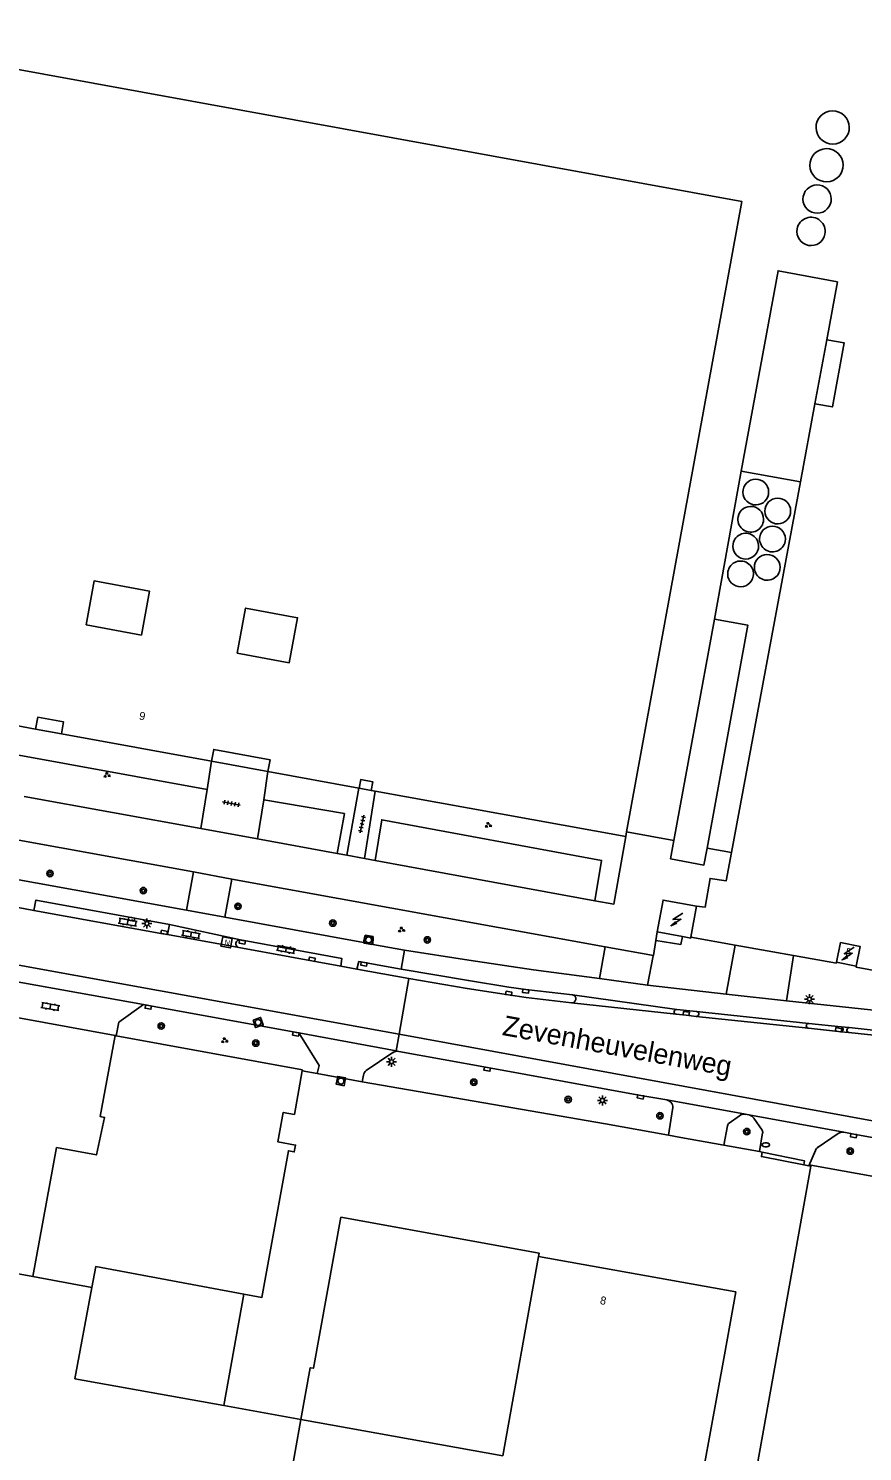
# Model space of a CAD drawing. Extents: x 130998 to 133001, y 398999 to 403002.
# Drawn here: x 132503.7 to 132608, y 399481.4 to 399659.2 of the extents above; entities that cross this region are included whole.
import ezdxf

# ---------------------------------------------------------------- set-up
doc = ezdxf.new("R2010")
doc.units = 0
for name, color, linetype in [('gg-afsc-erfafscheiding', 7, 'Continuous'), ('gg-afsc-hekwerk', 7, 'Continuous'), ('gg-anno-huisnummerreeks BGT', 7, 'Continuous'), ('gg-anno-openbare ruimte label', 7, 'Continuous'), ('gg-bbg-bijgebouw', 7, 'Continuous'), ('gg-bbg-gedigitaliseerde bebouwing', 7, 'Continuous'), ('gg-bbg-hoofdgebouw', 7, 'Continuous'), ('gg-bbg-luifel en loopbrug', 7, 'Continuous'), ('gg-bbg-opslagtank', 7, 'Continuous'), ('gg-bbg-tussenscheiding', 7, 'Continuous'), ('gg-knt-verharding', 7, 'Continuous'), ('gg-knt-verharding nz', 7, 'Continuous'), ('gt-grn-groengrens', 7, 'Continuous'), ('gt-grn-weggrens', 7, 'Continuous'), ('gt-symb-boom', 7, 'Continuous'), ('gt-symb-brandkraan', 7, 'Continuous'), ('gt-symb-groenvak', 7, 'Continuous'), ('gt-symb-klinker verharding', 7, 'Continuous'), ('gt-symb-kolk', 7, 'Continuous'), ('gt-symb-lichtmast', 7, 'Continuous'), ('gt-symb-nortonput', 7, 'Continuous'), ('gt-symb-rioolschacht', 7, 'Continuous'), ('gt-symb-tegel verharding', 7, 'Continuous'), ('gt-symb-trafo symbool', 7, 'Continuous')]:
    doc.layers.add(name, color=color, linetype=linetype)

# ---------------------------------------------------------------- blocks, each defined once
blk = doc.blocks.new('gt0-GRVAK')
at = {"layer": 'gt-symb-groenvak'}
for p, q in [((-0.11, 0.19), (-0.23, 0.24)), ((-0.18, 0.15), (0.09, 0.15)), ((-0.09, 0.21), (-0.16, 0.32)), ((-0.05, 0.21), (-0.05, 0.39)), ((0, 0.21), (0.06, 0.32)), ((0.01, 0.19), (0.13, 0.24)), ((0.26, -0.05), (0.2, 0.06)), ((0.3, -0.05), (0.3, 0.13)), ((0.35, -0.05), (0.41, 0.06)), ((-0.24, -0.23), (-0.36, -0.18)), ((-0.32, -0.26), (-0.05, -0.26)), ((-0.23, -0.21), (-0.29, -0.09)), ((-0.18, -0.2), (-0.18, -0.02)), ((-0.14, -0.21), (-0.07, -0.09)), ((-0.12, -0.23), (0, -0.18)), ((0.24, -0.07), (0.12, -0.02)), ((0.17, -0.11), (0.44, -0.11)), ((0.37, -0.07), (0.49, -0.02))]:
    blk.add_line(p, q, dxfattribs=at)
blk = doc.blocks.new('gt0-TEG1')
at = {"layer": 'gt-symb-tegel verharding'}
for p, q in [((-1.12, 0), (1.12, 0)), ((-0.9, -0.25), (-0.9, 0.25)), ((-0.45, -0.25), (-0.45, 0.25)), ((0, -0.25), (0, 0.25)), ((0.45, -0.25), (0.45, 0.25)), ((0.9, -0.25), (0.9, 0.25))]:
    blk.add_line(p, q, dxfattribs=at)
blk = doc.blocks.new('gt0-BOOM')
at = {"layer": 'gt-symb-boom'}
for radius in [0.4, 0.2]:
    blk.add_circle((0, 0), radius, dxfattribs=at)
blk = doc.blocks.new('gt0-RS')
at = {"layer": 'gt-symb-rioolschacht'}
blk.add_lwpolyline([(-0.5, -0.5), (0.5, -0.5), (0.5, 0.5), (-0.5, 0.5)], close=True, dxfattribs=at)
blk.add_circle((0, 0), 0.375, dxfattribs=at)
blk = doc.blocks.new('gt0-KL1')
at = {"layer": 'gt-symb-klinker verharding'}
for p, q in [((-1.15, 0.3), (1.15, 0.3)), ((-1, -0.3), (-1, 0.3)), ((-0.5, 0.3), (-0.5, 0.45)), ((0, -0.3), (0, 0.3)), ((0.5, 0.3), (0.5, 0.45)), ((1, -0.3), (1, 0.3)), ((-1.15, -0.3), (1.15, -0.3)), ((-0.5, -0.45), (-0.5, -0.3)), ((0.5, -0.45), (0.5, -0.3))]:
    blk.add_line(p, q, dxfattribs=at)
blk = doc.blocks.new('gt0-NPUT')
at = {"layer": 'gt-symb-nortonput'}
blk.add_lwpolyline([(-0.57, -0.61), (-0.57, 0.59), (0.63, 0.59), (0.63, -0.61)], close=True, dxfattribs=at)
blk.add_text('N', height=0.7, dxfattribs=at).set_placement((-0.22, -0.38))
blk = doc.blocks.new('gt0-KOLK')
at = {"layer": 'gt-symb-kolk'}
blk.add_lwpolyline([(0, 0), (0.37, 0), (0.37, 0.4), (-0.38, 0.4), (-0.38, 0), (0, 0)], dxfattribs=at)
blk = doc.blocks.new('gt0-LMAST')
at = {"layer": 'gt-symb-lichtmast'}
for p, q in [((-0.18, 0.17), (-0.45, 0.44)), ((-0.01, 0.25), (-0.01, 0.62)), ((0.17, 0.17), (0.44, 0.44)), ((-0.26, 0), (-0.63, 0)), ((-0.18, -0.18), (-0.45, -0.45)), ((-0.01, -0.25), (-0.01, -0.63)), ((0.44, -0.45), (0.17, -0.18)), ((0.24, 0), (0.62, 0))]:
    blk.add_line(p, q, dxfattribs=at)
blk.add_circle((-0.01, 0), 0.25, dxfattribs=at)
blk = doc.blocks.new('gt0-HSP')
at = {"layer": 'gt-symb-trafo symbool'}
for points in [[(0.77, 0.75), (-0.53, 0), (0.47, 0), (-0.83, -0.75)], [(-0.22, -0.24), (-0.83, -0.75), (-0.08, -0.48)]]:
    blk.add_lwpolyline(points, dxfattribs=at)
blk = doc.blocks.new('gt0-BR')
at = {"layer": 'gt-symb-brandkraan'}
for centre, radius, start, end in [((-0.24, 0), 0.206, 107.5669, 252.4331), ((0.6, -2.66), 3, 106.892, 107.5669), ((0, -0.69), 0.938, 73.108, 106.892), ((-0.6, -2.66), 3, 72.4331, 73.108), ((0.24, 0), 0.206, 287.567, 72.4331), ((0.6, 2.66), 3, 252.4331, 253.108), ((0, 0.69), 0.938, 253.108, 286.8921), ((-0.6, 2.66), 3, 286.8921, 287.567)]:
    blk.add_arc(centre, radius, start, end, dxfattribs=at)

msp = doc.modelspace()

# ---------------------------------------------------------------- linework, layer by layer
at = {"layer": 'gg-afsc-erfafscheiding'}
msp.add_line((132497.49, 399536.49), (132514.58, 399533.36), dxfattribs=at)
at = {"layer": 'gg-afsc-hekwerk'}
for p, q in [((132578.49, 399558.81), (132584.42, 399557.73)), ((132591.62, 399556.25), (132588.56, 399556.8)), ((132586.54, 399545.66), (132592.08, 399544.67)), ((132592.08, 399544.67), (132599.35, 399543.38)), ((132539.84, 399528.64), (132537.96, 399528.96)), ((132545.43, 399527.59), (132539.84, 399528.64)), ((132583.74, 399520.91), (132585.27, 399520.63)), ((132590.66, 399519.66), (132585.27, 399520.63)), ((132595.1, 399518.86), (132590.66, 399519.66)), ((132595.46, 399518.8), (132595.1, 399518.86)), ((132601.27, 399517.07), (132600.66, 399517.19))]:
    msp.add_line(p, q, dxfattribs=at)
for points in [[(132599.35, 399543.38), (132604.74, 399542.42), (132604.76, 399542.54)], [(132624.88, 399538.68), (132607.19, 399541.92), (132607.21, 399542.04)], [(132545.43, 399527.59), (132575.85, 399522.32), (132583.74, 399520.91)], [(132600.66, 399517.19), (132595.36, 399518.24), (132595.46, 399518.8)]]:
    msp.add_lwpolyline(points, dxfattribs=at)
at = {"layer": 'gg-bbg-bijgebouw'}
for p, q in [((132603.52, 399620.32), (132604.85, 399627.58)), ((132602.05, 399612.33), (132603.52, 399620.32)), ((132600.26, 399602.55), (132602.05, 399612.33)), ((132592.83, 399603.91), (132600.26, 399602.55)), ((132589.47, 399585.42), (132584.42, 399557.73)), ((132586.54, 399545.66), (132587.24, 399549.54)), ((132582.33, 399546.31), (132585.48, 399545.74)), ((132514.68, 399533.34), (132514.58, 399533.36)), ((132537.98, 399529.08), (132514.68, 399533.34)), ((132537.98, 399529.08), (132537.96, 399528.96)), ((132530.66, 399501.05), (132528.15, 399487.13)), ((132528.15, 399487.13), (132537.79, 399485.39))]:
    msp.add_line(p, q, dxfattribs=at)
for points in [[(132604.85, 399627.58), (132597.43, 399628.94), (132592.83, 399603.91)], [(132588.56, 399556.8), (132593.64, 399584.66), (132589.47, 399585.42)], [(132584.42, 399557.73), (132584, 399555.43), (132588.17, 399554.67), (132588.56, 399556.8)], [(132587.24, 399549.54), (132583.07, 399550.3), (132582.33, 399546.31)], [(132585.48, 399545.74), (132586.52, 399545.55), (132586.54, 399545.66)], [(132504.29, 399503.24), (132507.25, 399519.36), (132512.22, 399518.44), (132513.24, 399523.13), (132512.7, 399523.23), (132514.58, 399533.36)], [(132537.96, 399528.96), (132536.97, 399523.5), (132535.58, 399523.75), (132534.92, 399520.08), (132537.12, 399519.68), (132536.96, 399518.82), (132536.22, 399518.96), (132532.92, 399500.64), (132530.66, 399501.05)], [(132613.38, 399468.91), (132593.54, 399472.44), (132601.52, 399517.03)], [(132601.52, 399517.03), (132601.55, 399517.17), (132621.47, 399513.6)], [(132537.79, 399485.39), (132538.95, 399491.85), (132539.36, 399491.78), (132542.76, 399510.66)], [(132567.51, 399505.77), (132567.58, 399506.15), (132542.76, 399510.66)], [(132479.5, 399469.15), (132486.41, 399506.55), (132504.29, 399503.24)]]:
    msp.add_lwpolyline(points, dxfattribs=at)
at = {"layer": 'gg-bbg-gedigitaliseerde bebouwing'}
for points in [[(132510.93, 399584.68), (132517.85, 399583.41), (132518.86, 399588.92), (132511.94, 399590.19), (132510.93, 399584.68)], [(132529.84, 399581.15), (132536.34, 399579.96), (132537.37, 399585.59), (132530.87, 399586.78), (132529.84, 399581.15)]]:
    msp.add_lwpolyline(points, dxfattribs=at)
at = {"layer": 'gg-bbg-hoofdgebouw'}
for p, q in [((132459.74, 399579.83), (132504.62, 399571.67)), ((132507.85, 399571.08), (132526.63, 399567.64)), ((132533.66, 399566.36), (132545.04, 399564.29)), ((132545.04, 399564.29), (132545.08, 399564.28)), ((132546.57, 399564.01), (132547.06, 399563.92)), ((132547.06, 399563.92), (132578.39, 399558.23)), ((132578.39, 399558.23), (132578.49, 399558.81)), ((132604.76, 399542.54), (132607.21, 399542.04)), ((132592.17, 399501.33), (132567.51, 399505.77))]:
    msp.add_line(p, q, dxfattribs=at)
for points in [[(132578.49, 399558.81), (132592.89, 399637.61), (132474.31, 399659.23)], [(132504.62, 399571.67), (132504.89, 399573.15), (132508.12, 399572.57), (132507.85, 399571.08)], [(132526.63, 399567.64), (132526.9, 399569.12), (132533.93, 399567.84), (132533.66, 399566.36)], [(132545.08, 399564.28), (132545.28, 399565.35), (132546.76, 399565.08), (132546.57, 399564.01)], [(132607.21, 399542.04), (132607.71, 399544.49), (132605.26, 399544.99), (132604.76, 399542.54)], [(132592.17, 399501.33), (132590.74, 399493.44), (132586.45, 399469.96)]]:
    msp.add_lwpolyline(points, dxfattribs=at)
at = {"layer": 'gg-bbg-luifel en loopbrug'}
msp.add_lwpolyline([(132603.52, 399620.32), (132605.7, 399619.92), (132604.24, 399611.93), (132602.05, 399612.33)], dxfattribs=at)
at = {"layer": 'gg-bbg-opslagtank'}
for centre, radius, start, end in [((132604.26, 399646.86), 2.08, 349.4438, 169.4218), ((132604.26, 399646.86), 2.08, 169.4489, 349.4167), ((132603.49, 399642.13), 2.08, 349.4489, 169.4167), ((132603.49, 399642.14), 2.08, 169.4438, 349.4218), ((132602.32, 399637.91), 1.77, 169.425, 349.425), ((132602.32, 399637.91), 1.77, 349.425, 169.425), ((132601.56, 399633.86), 1.77, 349.428, 169.4538), ((132601.56, 399633.86), 1.77, 169.4597, 349.422), ((132594.65, 399601.29), 1.61, 349.4295, 169.4295), ((132594.65, 399601.29), 1.61, 169.4295, 349.4295), ((132594.02, 399597.89), 1.61, 349.4852, 169.4852), ((132597.4, 399598.92), 1.61, 169.4295, 349.4295), ((132597.4, 399598.92), 1.61, 349.4295, 169.4295), ((132594.02, 399597.89), 1.61, 169.4852, 349.4852), ((132593.39, 399594.53), 1.61, 349.412, 169.4535), ((132596.74, 399595.42), 1.61, 169.4852, 349.4852), ((132596.74, 399595.42), 1.61, 349.4852, 169.4852), ((132593.39, 399594.53), 1.61, 169.4535, 349.412), ((132592.75, 399591.06), 1.61, 349.447, 169.4885), ((132596.08, 399591.88), 1.61, 169.4502, 349.4502), ((132596.08, 399591.88), 1.61, 349.4502, 169.4502), ((132592.75, 399591.06), 1.61, 169.482, 349.4535)]:
    msp.add_arc(centre, radius, start, end, dxfattribs=at)
at = {"layer": 'gg-bbg-tussenscheiding'}
for p, q in [((132567.51, 399505.77), (132563.02, 399480.85)), ((132504.29, 399503.24), (132511.66, 399501.88)), ((132537.79, 399485.39), (132533.05, 399459.11)), ((132537.79, 399485.39), (132563.02, 399480.85))]:
    msp.add_line(p, q, dxfattribs=at)
for points in [[(132511.66, 399501.88), (132512.14, 399504.48), (132530.66, 399501.05)], [(132528.15, 399487.13), (132509.55, 399490.48), (132511.66, 399501.88)]]:
    msp.add_lwpolyline(points, dxfattribs=at)
at = {"layer": 'gg-knt-verharding'}
for p, q in [((132589.47, 399585.42), (132592.83, 399603.91)), ((132600.26, 399602.55), (132591.62, 399556.25)), ((132461.47, 399575.83), (132526.06, 399564.12)), ((132526.06, 399564.12), (132526.63, 399567.64)), ((132457.72, 399565.92), (132524.37, 399553.82)), ((132533.66, 399566.36), (132533.16, 399562.82)), ((132523.48, 399549.02), (132441.68, 399563.91)), ((132525.26, 399559.23), (132526.06, 399564.12)), ((132543.55, 399555.89), (132545.04, 399564.29)), ((132547.06, 399563.92), (132545.75, 399555.48)), ((132503.18, 399563.26), (132525.26, 399559.23)), ((132532.38, 399557.93), (132533.16, 399562.82)), ((132525.26, 399559.23), (132532.38, 399557.93)), ((132542.32, 399556.11), (132543.55, 399555.89)), ((132543.55, 399555.89), (132545.75, 399555.48)), ((132545.75, 399555.48), (132547.09, 399555.24)), ((132523.48, 399549.02), (132524.37, 399553.82)), ((132529.16, 399552.93), (132528.28, 399548.16)), ((132575.84, 399544.44), (132529.16, 399552.93)), ((132502.45, 399549.36), (132504.42, 399549)), ((132504.42, 399549), (132520.53, 399546.08)), ((132523.48, 399549.02), (132528.28, 399548.16)), ((132528.28, 399548.16), (132545.61, 399544.98)), ((132521.11, 399545.98), (132520.53, 399546.08)), ((132521.35, 399547.26), (132521.11, 399545.98)), ((132521.11, 399545.98), (132530.04, 399544.36)), ((132521.35, 399547.26), (132530.22, 399545.32)), ((132582.16, 399545.25), (132582.33, 399546.31)), ((132530.04, 399544.36), (132542.78, 399542.03)), ((132546.79, 399544.75), (132550.74, 399544.03)), ((132550.74, 399544.03), (132550.32, 399541.67)), ((132575.84, 399544.44), (132575.13, 399540.5)), ((132581.85, 399543.38), (132582.16, 399545.25)), ((132592.08, 399544.67), (132590.94, 399538.52)), ((132542.78, 399542.03), (132544.8, 399541.66)), ((132544.8, 399541.66), (132545.02, 399542.62)), ((132545.02, 399542.62), (132550.32, 399541.67)), ((132581.84, 399543.32), (132581.13, 399539.67)), ((132581.84, 399543.32), (132581.85, 399543.38)), ((132599.35, 399543.38), (132598.5, 399537.7)), ((132496.36, 399541.17), (132518.1, 399537.23)), ((132544.8, 399541.66), (132551.26, 399540.51)), ((132550.06, 399533.52), (132551.26, 399540.51)), ((132575.13, 399540.5), (132581.13, 399539.67)), ((132571.75, 399538.44), (132584.78, 399536.64)), ((132581.13, 399539.67), (132590.94, 399538.52)), ((132590.94, 399538.52), (132598.5, 399537.7)), ((132518.1, 399537.23), (132520.32, 399536.82)), ((132520.32, 399536.82), (132537.55, 399533.69)), ((132571.62, 399537.44), (132584.69, 399536.03)), ((132584.78, 399536.64), (132587.26, 399536.37)), ((132587.2, 399535.76), (132601.23, 399534.27)), ((132587.26, 399536.37), (132601.28, 399534.88)), ((132601.28, 399534.88), (132605.31, 399534.45)), ((132549.68, 399531.47), (132537.55, 399533.69)), ((132549.68, 399531.47), (132550.06, 399533.52)), ((132605.24, 399533.84), (132606.3, 399533.73)), ((132605.31, 399534.45), (132606.34, 399534.35)), ((132606.34, 399534.35), (132625.75, 399532.24)), ((132550.03, 399531.39), (132549.68, 399531.47)), ((132549.29, 399531.23), (132545.96, 399528.99)), ((132545.61, 399528.42), (132545.43, 399527.59)), ((132593.35, 399523.52), (132583.52, 399525.32)), ((132583.74, 399520.91), (132584.26, 399524.13)), ((132592.6, 399523.35), (132591.31, 399522.43)), ((132593.8, 399523.44), (132593.35, 399523.52)), ((132605.67, 399521.29), (132593.8, 399523.44)), ((132595.44, 399521.55), (132594.4, 399523.03)), ((132591.11, 399522.09), (132590.66, 399519.66)), ((132595.1, 399518.86), (132595.51, 399521.19)), ((132604.95, 399521.12), (132602.46, 399519.43)), ((132602.11, 399519.01), (132601.27, 399517.07)), ((132601.27, 399517.07), (132601.52, 399517.03))]:
    msp.add_line(p, q, dxfattribs=at)
for points in [[(132542.32, 399556.11), (132543.23, 399561.11), (132533.16, 399562.82)], [(132547.09, 399555.24), (132547.89, 399560.33), (132575.38, 399555.25), (132574.55, 399550.22)], [(132574.55, 399550.22), (132576.91, 399549.79), (132578.39, 399558.23)], [(132591.62, 399556.25), (132590.96, 399552.71), (132588.94, 399553.01), (132588.33, 399549.42), (132587.24, 399549.54)], [(132521.35, 399547.26), (132504.67, 399550.3), (132504.42, 399549)], [(132545.61, 399544.98), (132545.77, 399545.77), (132546.84, 399545.57), (132546.79, 399544.75)], [(132585.48, 399545.74), (132585.28, 399544.74), (132582.16, 399545.25)], [(132530.22, 399545.32), (132542.92, 399542.99), (132542.78, 399542.03)], [(132550.74, 399544.03), (132558.79, 399542.78), (132566.86, 399541.56), (132575.13, 399540.5)], [(132550.32, 399541.67), (132558.73, 399540.23), (132563.8, 399539.41), (132565.9, 399539.11), (132571.75, 399538.44)], [(132551.26, 399540.51), (132558.58, 399539.25), (132563.75, 399538.44), (132565.94, 399538.12), (132571.62, 399537.44)], [(132518.1, 399537.23), (132515.02, 399535.03), (132514.68, 399533.34)], [(132598.5, 399537.7), (132620.64, 399535.34), (132641.51, 399533.08), (132659.12, 399531.23)], [(132584.69, 399536.03), (132585.93, 399535.92), (132587.2, 399535.76)], [(132539.84, 399528.64), (132540.08, 399529.62), (132537.55, 399533.69)], [(132601.23, 399534.27), (132604.98, 399533.89), (132605.24, 399533.84)], [(132606.3, 399533.73), (132625.4, 399531.69), (132625.68, 399531.64)], [(132583.52, 399525.32), (132580.27, 399525.89), (132561.11, 399529.36), (132550.03, 399531.39)], [(132620.96, 399518.49), (132618.2, 399518.98), (132606.91, 399521.05), (132605.67, 399521.29)], [(132600.66, 399517.19), (132600.76, 399517.69), (132595.46, 399518.8)]]:
    msp.add_lwpolyline(points, dxfattribs=at)
for centre, radius, start, end in [((132530.14, 399544.83), 0.49, 80.6777, 258.0327), ((132571.65, 399537.94), 0.505, 265.8608, 78.6345), ((132584.75, 399536.33), 0.308, 85.3767, 257.571), ((132587.22, 399536.07), 0.308, 266.171, 83.2042), ((132601.27, 399534.57), 0.305, 88.0725, 263.4478), ((132605.26, 399534.15), 0.308, 266.4508, 81.4043), ((132606.34, 399534.04), 0.31, 90.713, 262.8041), ((132549.87, 399530.38), 1.02, 80.7671, 124.535), ((132546.49, 399528.27), 0.898, 126.2306, 170.4767), ((132583.29, 399524.35), 0.995, 347.1661, 76.3229), ((132591.6, 399522.03), 0.491, 126.0226, 172.3549), ((132593.18, 399522.51), 1.02, 80.8137, 124.7483), ((132593.56, 399522.45), 1.02, 34.7813, 76.1606), ((132594.99, 399521.27), 0.529, 351.3533, 32.1199), ((132605.51, 399520.29), 1, 81.1742, 124.1372), ((132603.05, 399518.58), 1.04, 124.487, 155.3698)]:
    msp.add_arc(centre, radius, start, end, dxfattribs=at)
at = {"layer": 'gg-knt-verharding nz'}
for p, q in [((132532.38, 399557.93), (132542.32, 399556.11)), ((132547.09, 399555.24), (132574.55, 399550.22)), ((132550.06, 399533.52), (132439.77, 399553.58)), ((132524.37, 399553.82), (132529.16, 399552.93)), ((132581.85, 399543.38), (132575.84, 399544.44))]:
    msp.add_line(p, q, dxfattribs=at)
msp.add_lwpolyline([(132647.67, 399515.56), (132642.25, 399516.71), (132621.09, 399520.55), (132550.06, 399533.52)], dxfattribs=at)
at = {"layer": 'gt-grn-groengrens'}
msp.add_line((132504.62, 399571.67), (132507.85, 399571.08), dxfattribs=at)
at = {"layer": 'gt-grn-weggrens'}
for p, q in [((132526.63, 399567.64), (132533.66, 399566.36)), ((132545.08, 399564.28), (132546.57, 399564.01)), ((132545.61, 399544.98), (132546.79, 399544.75))]:
    msp.add_line(p, q, dxfattribs=at)

# ---------------------------------------------------------------- block references
at = {"layer": 'gt-symb-boom'}
for p in [(132506.42, 399553.62), (132518.09, 399551.48), (132529.92, 399549.52), (132541.78, 399547.42), (132553.59, 399545.32), (132520.33, 399534.56), (132532.15, 399532.42), (132559.4, 399527.53), (132571.2, 399525.37), (132582.67, 399523.34), (132593.52, 399521.36), (132606.46, 399518.92)]:
    msp.add_blockref('gt0-BOOM', p, dxfattribs=at)
at = {"layer": 'gt-symb-brandkraan'}
msp.add_blockref('gt0-BR', (132595.9, 399519.7), dxfattribs=at)
at = {"layer": 'gt-symb-groenvak'}
for p, rotation in [((132513.53, 399565.92), -10.309970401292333), ((132561.19, 399559.66), -10.30997039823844), ((132550.34, 399546.58), -10.309970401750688), ((132528.23, 399532.74), -10.30997039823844)]:
    msp.add_blockref('gt0-GRVAK', p, dxfattribs=dict(at, rotation=rotation))
at = {"layer": 'gt-symb-klinker verharding'}
for p, rotation in [((132516.14, 399547.52), 169.8027944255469), ((132524.05, 399546), -10.48938981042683), ((132535.92, 399544.13), 169.34163849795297), ((132506.47, 399536.98), -10.30997039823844)]:
    msp.add_blockref('gt0-KL1', p, dxfattribs=dict(at, rotation=rotation))
at = {"layer": 'gt-symb-kolk'}
for p, rotation in [((132516.64, 399548.11), 169.63367739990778), ((132520.67, 399546.06), -10.197205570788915), ((132530.49, 399545.25), 169.69002960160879), ((132539.15, 399542.7), -10.4330247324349), ((132545.7, 399542.5), 169.69002960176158), ((132563.75, 399538.44), -8.349214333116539), ((132565.9, 399539.11), 171.96804975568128), ((132518.74, 399537.11), 170.0949207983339), ((132585.93, 399535.92), -7.128019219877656), ((132537.19, 399533.76), 169.74640197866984), ((132604.98, 399533.89), -10.050052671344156), ((132561.11, 399529.36), 169.61431705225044), ((132580.27, 399525.89), 169.73629769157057), ((132606.91, 399521.05), 169.22815913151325)]:
    msp.add_blockref('gt0-KOLK', p, dxfattribs=dict(at, rotation=rotation))
at = {"layer": 'gt-symb-lichtmast'}
for p in [(132518.55, 399547.36), (132601.37, 399537.92), (132549.13, 399530.09), (132575.49, 399525.26)]:
    msp.add_blockref('gt0-LMAST', p, dxfattribs=at)
at = {"layer": 'gt-symb-nortonput', "rotation": -10.36632260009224}
msp.add_blockref('gt0-NPUT', (132528.47, 399545.03), dxfattribs=at)
at = {"layer": 'gt-symb-rioolschacht'}
for p, rotation in [((132546.25, 399545.32), 170.84860398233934), ((132532.44, 399535), -70.7315850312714), ((132542.79, 399527.68), 78.92612884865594)]:
    msp.add_blockref('gt0-RS', p, dxfattribs=dict(at, rotation=rotation))
at = {"layer": 'gt-symb-tegel verharding'}
for p, rotation in [((132529.11, 399562.36), -10.366322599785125), ((132545.43, 399559.81), 77.52092819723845)]:
    msp.add_blockref('gt0-TEG1', p, dxfattribs=dict(at, rotation=rotation))
at = {"layer": 'gt-symb-trafo symbool'}
for p, rotation in [((132584.82, 399547.88), 3.2116257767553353), ((132606.23, 399543.62), 3.2116257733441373)]:
    msp.add_blockref('gt0-HSP', p, dxfattribs=dict(at, rotation=rotation))

# ---------------------------------------------------------------- texts
at = {"layer": 'gg-anno-huisnummerreeks BGT'}
for s, rotation, p in [('9', 349.6, (132517.51, 399572.87)), ('5', 348.5, (132605.8, 399543.35)), ('8', 349.8, (132575.13, 399499.82))]:
    msp.add_text(s, height=1, rotation=rotation, dxfattribs=at).set_placement(p)
at = {"layer": 'gg-anno-openbare ruimte label'}
msp.add_text('Zevenheuvelenweg', height=2.5, rotation=349.7, dxfattribs=at).set_placement((132562.86, 399533.44))

doc.saveas('drawing.dxf')
